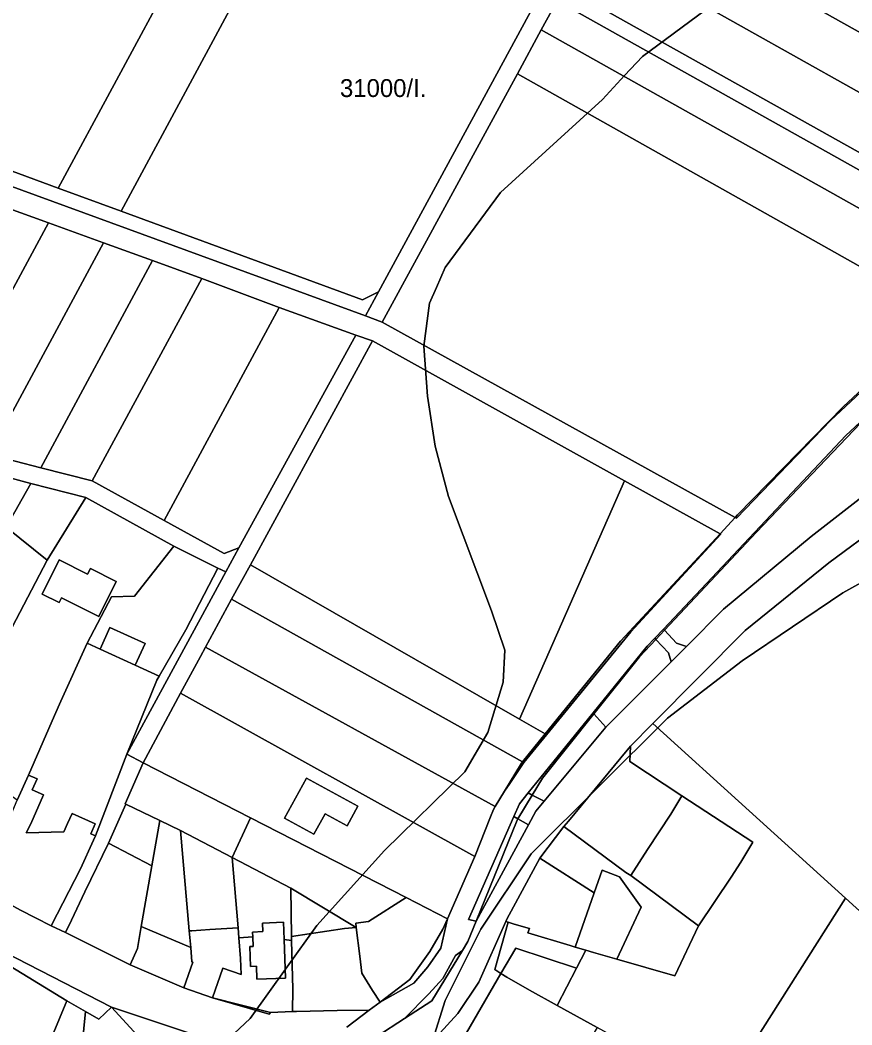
# Model space of a CAD drawing. Extents: x -541351 to -537540, y -1162694 to -1159725.
# Drawn here: x -538217.7 to -537985.1, y -1161335.8 to -1161054.8 of the extents above; entities that cross this region are included whole.
import ezdxf

# ---------------------------------------------------------------- set-up
doc = ezdxf.new("R2010")
doc.units = 0
for name, color, linetype in [('95560013', 7, 'Continuous'), ('95590013', 7, 'Continuous'), ('95610013', 7, 'Continuous'), ('95630013', 7, 'Continuous'), ('95640013', 7, 'Continuous'), ('95660013', 7, 'Continuous')]:
    doc.layers.add(name, color=color, linetype=linetype)

msp = doc.modelspace()

# ---------------------------------------------------------------- linework, layer by layer
at = {"layer": '95560013'}
for points in [[(-538246.11, -1161087.46), (-538182.74, -1160971.35), (-538141.8, -1160980.88), (-538207.03, -1161101.81), (-538233.61, -1161092.05)], [(-538141.8, -1160980.88), (-538123.2, -1160985.21), (-538189.43, -1161108.27), (-538207.03, -1161101.81)], [(-538050.98, -1161002.02), (-538049.53, -1161005.48), (-538117.46, -1161130.76), (-538121.93, -1161133.04), (-538189.43, -1161108.27), (-538123.2, -1160985.21)], [(-537903.69, -1161085.29), (-537915.45, -1161096.02), (-538051.5, -1161019.74), (-538044.43, -1161006.74)], [(-537941.41, -1161120.13), (-537948.57, -1161126.77), (-538071.97, -1161057.57), (-538067.56, -1161049.39)], [(-538071.97, -1161057.57), (-537948.57, -1161126.77), (-537959.49, -1161136.9), (-538078.6, -1161069.87)], [(-538017.76, -1161193.9), (-538116.49, -1161139.32), (-538078.6, -1161069.87), (-537959.49, -1161136.9), (-537987.47, -1161162.86), (-538017.1, -1161193.19)], [(-538166.87, -1161127.08), (-538145.25, -1161135.18), (-538177.41, -1161194.75), (-538197.52, -1161183.69)], [(-537862.95, -1161412.71), (-537904.74, -1161473.13), (-537909.29, -1161473.5), (-537958.26, -1161439.63), (-538014.16, -1161400.98), (-537997.12, -1161376.05), (-538023.45, -1161358.02), (-537986.93, -1161300.34), (-537910.48, -1161369.63)]]:
    msp.add_lwpolyline(points, close=True, dxfattribs=at)
msp.add_lwpolyline([(-537910.48, -1161369.63), (-537986.93, -1161300.34), (-538040.75, -1161251.55), (-538014.94, -1161225.48), (-537991.61, -1161206.61), (-537962.32, -1161184.95)], dxfattribs=at)
at = {"layer": '95590013'}
for points in [[(-537915.45, -1161096.02), (-537926.78, -1161106.53), (-538058.53, -1161032.66), (-538051.5, -1161019.74)], [(-537938.08, -1161117.04), (-538065.5, -1161045.58), (-538058.53, -1161032.66), (-537926.78, -1161106.53)], [(-537938.08, -1161117.04), (-537941.41, -1161120.13), (-538067.56, -1161049.39), (-538065.5, -1161045.58)], [(-538248.97, -1161170.34), (-538253.63, -1161166.17), (-538221.89, -1161107.13), (-538209.76, -1161111.53), (-538242.45, -1161172.06)], [(-538242.45, -1161172.06), (-538209.76, -1161111.53), (-538194.34, -1161117.12), (-538226.3, -1161176.33)], [(-538226.3, -1161176.33), (-538194.34, -1161117.12), (-538180.71, -1161122.06), (-538211.86, -1161180.02)], [(-538180.71, -1161122.06), (-538166.87, -1161127.08), (-538197.52, -1161183.69), (-538211.86, -1161180.02)], [(-538145.25, -1161135.18), (-538123.8, -1161142.88), (-538156.51, -1161202.37), (-538160.59, -1161204), (-538177.41, -1161194.75)], [(-538228.93, -1161180.63), (-538214.72, -1161184.39), (-538221.56, -1161196.64), (-538233.17, -1161188.12)], [(-538221.56, -1161196.64), (-538214.72, -1161184.39), (-538199.3, -1161188.32), (-538210.1, -1161205.84)], [(-538185.68, -1161215.95), (-538192.12, -1161216.12), (-538198.98, -1161229.08), (-538206.32, -1161245.29), (-538208.04, -1161249.25), (-538215.35, -1161265.95), (-538218.47, -1161272.98), (-538226.43, -1161267.38), (-538222.55, -1161258.47), (-538228.24, -1161255.93), (-538232.5, -1161265.65), (-538239.68, -1161262.59), (-538233.03, -1161249.61), (-538210.1, -1161205.84), (-538199.3, -1161188.32), (-538174.67, -1161201.96)], [(-538221.56, -1161196.64), (-538210.1, -1161205.84), (-538233.03, -1161249.61), (-538242.07, -1161245.33), (-538252.02, -1161240.61), (-538234.58, -1161212.88), (-538229.57, -1161215.15), (-538226.63, -1161208.69), (-538231.63, -1161206.42)], [(-538182.74, -1161229.12), (-538192.57, -1161224.66), (-538195.33, -1161230.76), (-538198.98, -1161229.08), (-538192.12, -1161216.12), (-538185.68, -1161215.95), (-538174.67, -1161201.96), (-538162.39, -1161208.04), (-538171.35, -1161225.31), (-538178.84, -1161238.26), (-538185.51, -1161235.2)], [(-538206.11, -1161216.38), (-538195.64, -1161221.58), (-538190.79, -1161211.81), (-538198.04, -1161208.21), (-538198.8, -1161209.74), (-538206.77, -1161205.78), (-538211.53, -1161215.36), (-538206.78, -1161217.72)], [(-538171.35, -1161225.31), (-538162.39, -1161208.04), (-538160.18, -1161209.13), (-538187.83, -1161260.14), (-538179.48, -1161239.38), (-538178.84, -1161238.26)], [(-538082.21, -1161270.41), (-538084.82, -1161274.71), (-538165.84, -1161230.16), (-538158.58, -1161216.8), (-538077.18, -1161262.24), (-538077.49, -1161262.62)], [(-538172.84, -1161243.04), (-538167.26, -1161232.77), (-538165.84, -1161230.16), (-538084.82, -1161274.71), (-538085.32, -1161275.54), (-538086.13, -1161277.58), (-538090.55, -1161288.74)], [(-538153.25, -1161277.88), (-538183.26, -1161262.48), (-538172.84, -1161243.04), (-538090.55, -1161288.74), (-538098.16, -1161306.15), (-538109.73, -1161300.22)], [(-538048.87, -1161340.61), (-538056.37, -1161336.5), (-538067.49, -1161330.41), (-538062.1, -1161319.97), (-538059.49, -1161314.92), (-538057.35, -1161315.54), (-538050.81, -1161317.42), (-538034.67, -1161322.06), (-538028, -1161308.15), (-538018.91, -1161294.47), (-538016.19, -1161290.33), (-538012.78, -1161284.73), (-538032.67, -1161271.71), (-538047.23, -1161262.17), (-538047.04, -1161257.9), (-538040.75, -1161251.55), (-537986.93, -1161300.34), (-538023.45, -1161358.02)], [(-538032.67, -1161271.71), (-538035.76, -1161276.86), (-538042.23, -1161286.72), (-538046.89, -1161294), (-538048.32, -1161293.16), (-538065.66, -1161280.36), (-538064.4, -1161278.84), (-538049.68, -1161261.08), (-538047.04, -1161257.9), (-538047.23, -1161262.17)], [(-538183.26, -1161262.48), (-538153.25, -1161277.88), (-538158.35, -1161289.03), (-538172.86, -1161281.42), (-538178.64, -1161278.63), (-538188.09, -1161274.06), (-538188.28, -1161273.97)], [(-538123.25, -1161274.64), (-538137.61, -1161266.79), (-538143.78, -1161277.98), (-538135.54, -1161282.51), (-538132.37, -1161276.76), (-538126.24, -1161280.1)], [(-538169.99, -1161314.15), (-538183.84, -1161308.34), (-538180.86, -1161291.3), (-538178.64, -1161278.63), (-538172.86, -1161281.42), (-538170.44, -1161309.54)], [(-538123.73, -1161308.57), (-538141.98, -1161297.6), (-538158.35, -1161289.03), (-538153.25, -1161277.88), (-538109.73, -1161300.22), (-538120.27, -1161306.94), (-538123.84, -1161307.38)], [(-538050.07, -1161294.4), (-538054.93, -1161292.56), (-538057.14, -1161298.88), (-538072.34, -1161289.23), (-538065.66, -1161280.36), (-538048.32, -1161293.16), (-538046.89, -1161294), (-538028, -1161308.15), (-538034.67, -1161322.06), (-538050.81, -1161317.42), (-538044.08, -1161302.9)], [(-538172.86, -1161281.42), (-538158.35, -1161289.03), (-538156.75, -1161308.71), (-538164.64, -1161309.17), (-538169.67, -1161309.49), (-538170.44, -1161309.54)], [(-538141.98, -1161297.6), (-538141.83, -1161311.11), (-538141.82, -1161312.2), (-538143.89, -1161311.92), (-538144.07, -1161307.13), (-538149.89, -1161307.33), (-538149.78, -1161309.71), (-538152.71, -1161309.85), (-538152.66, -1161311.14), (-538156.52, -1161311.46), (-538156.75, -1161308.71), (-538158.35, -1161289.03)], [(-538141.83, -1161311.11), (-538141.98, -1161297.6), (-538123.73, -1161308.57), (-538127.02, -1161308.88)], [(-538067.49, -1161330.41), (-538075.29, -1161326.14), (-538081.56, -1161322.5), (-538083.28, -1161321.48), (-538079.07, -1161314.31), (-538062.1, -1161319.97)], [(-538201.63, -1161354.88), (-538202.9, -1161363.74), (-538204.4, -1161363.88), (-538203.87, -1161369.63), (-538205.58, -1161379.99), (-538216.91, -1161379.32), (-538216.87, -1161370.22), (-538212.13, -1161351.43), (-538208.75, -1161339), (-538204.65, -1161329.08), (-538199.37, -1161332.11)]]:
    msp.add_lwpolyline(points, close=True, dxfattribs=at)
at = {"layer": '95610013'}
for points in [[(-537996.47, -1161199.19), (-538020.98, -1161219.57), (-538031.39, -1161229.99), (-538034.17, -1161229.06), (-538037.53, -1161225.44), (-538011.8, -1161198.06), (-537982.73, -1161167.56), (-537948.84, -1161136.22), (-537936.28, -1161153.8), (-537968.86, -1161177.68)], [(-538153.28, -1161207.14), (-538119.15, -1161144.52), (-538048.69, -1161183.64), (-538078.07, -1161250.34)], [(-538070.89, -1161254.46), (-538078.07, -1161250.34), (-538048.69, -1161183.64), (-538021.99, -1161198.46), (-538049.86, -1161228.47)], [(-538070.89, -1161254.46), (-538077.18, -1161262.24), (-538158.58, -1161216.8), (-538153.28, -1161207.14), (-538078.07, -1161250.34)], [(-538036.42, -1161231.78), (-538039.94, -1161228.01), (-538037.53, -1161225.44), (-538034.17, -1161229.06), (-538031.39, -1161229.99), (-538035.64, -1161234.24)], [(-538039.94, -1161228.01), (-538036.42, -1161231.78), (-538035.64, -1161234.24), (-538053.92, -1161252.54), (-538057.25, -1161248.83), (-538044.49, -1161232.86)]]:
    msp.add_lwpolyline(points, close=True, dxfattribs=at)
at = {"layer": '95630013'}
for points in [[(-537867.27, -1161068.59), (-537867, -1161069.02), (-537887.98, -1161079.94), (-537948.84, -1161136.22), (-537982.73, -1161167.56), (-538011.8, -1161198.06), (-538037.53, -1161225.44), (-538037.84, -1161225.1), (-537986.78, -1161171.01), (-537949.05, -1161135.92), (-537888.93, -1161079.99)], [(-538017.1, -1161193.19), (-537987.47, -1161162.86), (-537959.49, -1161136.9), (-537959.19, -1161137.07), (-537990.97, -1161166.65), (-538017.4, -1161194.1), (-538017.76, -1161193.9)], [(-538076.87, -1161262.41), (-538077.18, -1161262.24), (-538070.89, -1161254.46), (-538049.86, -1161228.47), (-538021.99, -1161198.46), (-538021.73, -1161198.6), (-538046.97, -1161225.92)], [(-538039.94, -1161228.01), (-538040.26, -1161227.67), (-538037.84, -1161225.1), (-538037.53, -1161225.44)], [(-538044.49, -1161232.86), (-538057.25, -1161248.83), (-538057.48, -1161248.57), (-538042.4, -1161229.94), (-538040.26, -1161227.67), (-538039.94, -1161228.01)], [(-538071.63, -1161266.84), (-538074.49, -1161271.55), (-538075.61, -1161270.96), (-538057.48, -1161248.57), (-538057.25, -1161248.83)], [(-538082.21, -1161270.41), (-538077.49, -1161262.62), (-538077.18, -1161262.24), (-538076.87, -1161262.41), (-538080.78, -1161268.27)], [(-538074.49, -1161271.55), (-538078.51, -1161278.18), (-538079.64, -1161277.56), (-538078.09, -1161274.02), (-538075.61, -1161270.96)], [(-538092.28, -1161306.35), (-538079.64, -1161277.56), (-538078.51, -1161278.18), (-538078.74, -1161278.56), (-538090.17, -1161306.77)], [(-538098.16, -1161306.15), (-538100.05, -1161314.32), (-538103.67, -1161319.58), (-538107.62, -1161324.11), (-538117.04, -1161329.42), (-538108.69, -1161323.1), (-538103.16, -1161315.27), (-538099.45, -1161309.07)], [(-538094.04, -1161315.05), (-538102.54, -1161329.13), (-538110.22, -1161334.06), (-538103.41, -1161327.15), (-538099.5, -1161322.86), (-538095.94, -1161316.37)]]:
    msp.add_lwpolyline(points, close=True, dxfattribs=at)
for points in [[(-538292.2, -1161074.93), (-538121.13, -1161137.53), (-538116.49, -1161139.32), (-538017.76, -1161193.9), (-538021.99, -1161198.46), (-538048.69, -1161183.64), (-538119.15, -1161144.52), (-538123.8, -1161142.88), (-538145.25, -1161135.18), (-538166.87, -1161127.08), (-538180.71, -1161122.06), (-538194.34, -1161117.12), (-538209.76, -1161111.53), (-538221.89, -1161107.13)], [(-538126.38, -1161336.49), (-538120.06, -1161331.71), (-538117.04, -1161329.42), (-538107.62, -1161324.11), (-538103.67, -1161319.58), (-538100.05, -1161314.32), (-538098.16, -1161306.15), (-538090.55, -1161288.74), (-538086.13, -1161277.58), (-538085.32, -1161275.54), (-538084.82, -1161274.71), (-538082.21, -1161270.41), (-538080.78, -1161268.27), (-538076.87, -1161262.41), (-538046.97, -1161225.92), (-538021.73, -1161198.6), (-538021.99, -1161198.46), (-538017.76, -1161193.9), (-538017.4, -1161194.1), (-537990.97, -1161166.65), (-537959.19, -1161137.07)], [(-537949.05, -1161135.92), (-537986.78, -1161171.01), (-538037.84, -1161225.1), (-538040.26, -1161227.67), (-538042.4, -1161229.94), (-538057.48, -1161248.57), (-538075.61, -1161270.96), (-538078.09, -1161274.02), (-538079.64, -1161277.56), (-538092.28, -1161306.35), (-538090.17, -1161306.77), (-538092.49, -1161312.48), (-538094.04, -1161315.05), (-538095.94, -1161316.37), (-538099.5, -1161322.86), (-538103.41, -1161327.15), (-538110.22, -1161334.06), (-538117.98, -1161339.05)]]:
    msp.add_lwpolyline(points, dxfattribs=at)
at = {"layer": '95640013'}
for points in [[(-538049.53, -1161005.48), (-538050.98, -1161002.02), (-538039.9, -1161004.61), (-538044.43, -1161006.74), (-538051.5, -1161019.74), (-538058.53, -1161032.66), (-538065.5, -1161045.58), (-538067.56, -1161049.39), (-538071.97, -1161057.57), (-538078.6, -1161069.87), (-538116.49, -1161139.32), (-538121.13, -1161137.53), (-538117.46, -1161130.76)], [(-538119.15, -1161144.52), (-538153.28, -1161207.14), (-538158.58, -1161216.8), (-538165.84, -1161230.16), (-538167.26, -1161232.77), (-538172.84, -1161243.04), (-538183.26, -1161262.48), (-538187.83, -1161260.14), (-538160.18, -1161209.13), (-538156.51, -1161202.37), (-538123.8, -1161142.88)], [(-538206.78, -1161217.72), (-538211.53, -1161215.36), (-538206.77, -1161205.78), (-538198.8, -1161209.74), (-538198.04, -1161208.21), (-538190.79, -1161211.81), (-538195.64, -1161221.58), (-538206.11, -1161216.38)], [(-538192.57, -1161224.66), (-538182.74, -1161229.12), (-538185.51, -1161235.2), (-538195.33, -1161230.76)], [(-538208.04, -1161249.25), (-538206.32, -1161245.29), (-538198.98, -1161229.08), (-538195.33, -1161230.76), (-538185.51, -1161235.2), (-538178.84, -1161238.26), (-538179.48, -1161239.38), (-538187.83, -1161260.14), (-538196.6, -1161282.98), (-538197.91, -1161282.41), (-538196.73, -1161279.61), (-538203.14, -1161276.7), (-538204.45, -1161279.52), (-538205.49, -1161281.78), (-538216.01, -1161282.13), (-538214.7, -1161279.55), (-538211.13, -1161271.46), (-538214.28, -1161270.05), (-538212.96, -1161267), (-538215.35, -1161265.95)], [(-538074.49, -1161271.55), (-538071.63, -1161266.84), (-538057.25, -1161248.83), (-538053.92, -1161252.54), (-538071.16, -1161273.29)], [(-538200.82, -1161292.15), (-538197.13, -1161284.14), (-538196.6, -1161282.98), (-538187.83, -1161260.14), (-538183.26, -1161262.48), (-538188.28, -1161273.97), (-538188.09, -1161274.06), (-538192.99, -1161284.98), (-538199.55, -1161298.56), (-538203.3, -1161306.56), (-538204.96, -1161309.98), (-538209.04, -1161308.12)], [(-538196.6, -1161282.98), (-538197.13, -1161284.14), (-538200.82, -1161292.15), (-538209.04, -1161308.12), (-538213.35, -1161305.89), (-538217.56, -1161303.7), (-538231.47, -1161296.16), (-538228.59, -1161291.79), (-538227.33, -1161289.9), (-538224.32, -1161285.3), (-538220.21, -1161276.97), (-538218.47, -1161272.98), (-538215.35, -1161265.95), (-538212.96, -1161267), (-538214.28, -1161270.05), (-538211.13, -1161271.46), (-538214.7, -1161279.55), (-538216.01, -1161282.13), (-538205.49, -1161281.78), (-538204.45, -1161279.52), (-538203.14, -1161276.7), (-538196.73, -1161279.61), (-538197.91, -1161282.41)], [(-538143.78, -1161277.98), (-538137.61, -1161266.79), (-538123.25, -1161274.64), (-538126.24, -1161280.1), (-538132.37, -1161276.76), (-538135.54, -1161282.51)], [(-538075.51, -1161279.83), (-538078.51, -1161278.18), (-538074.49, -1161271.55), (-538071.16, -1161273.29), (-538073.45, -1161276.05)], [(-538012.78, -1161284.73), (-538016.19, -1161290.33), (-538018.91, -1161294.47), (-538028, -1161308.15), (-538046.89, -1161294), (-538042.23, -1161286.72), (-538035.76, -1161276.86), (-538032.67, -1161271.71)], [(-538192.99, -1161284.98), (-538188.09, -1161274.06), (-538178.64, -1161278.63), (-538180.86, -1161291.3)], [(-538192.16, -1161330.85), (-538195.72, -1161334.2), (-538199.37, -1161332.11), (-538204.65, -1161329.08), (-538229.72, -1161313.75), (-538236.28, -1161309.78), (-538238.78, -1161308.21), (-538245.54, -1161304.08), (-538251.65, -1161301.22), (-538274.94, -1161293.48), (-538276.06, -1161296.55), (-538307.06, -1161285.3), (-538308.93, -1161290.39), (-538312.04, -1161297.25), (-538308.26, -1161282.74), (-538303.02, -1161280.34), (-538245.31, -1161303.55)], [(-538078.74, -1161278.56), (-538078.51, -1161278.18), (-538075.51, -1161279.83), (-538090.17, -1161306.77)], [(-538204.96, -1161309.98), (-538203.3, -1161306.56), (-538199.55, -1161298.56), (-538192.99, -1161284.98), (-538180.86, -1161291.3), (-538183.84, -1161308.34), (-538184.9, -1161314.44), (-538186.92, -1161319.02)], [(-538081.21, -1161307.11), (-538081.87, -1161306.89), (-538081.57, -1161306.27), (-538072.34, -1161289.23), (-538057.14, -1161298.88), (-538062.46, -1161314.06), (-538063.88, -1161313.65), (-538075.74, -1161310.03), (-538075.3, -1161308.85), (-538079.54, -1161307.64)], [(-538062.46, -1161314.06), (-538057.14, -1161298.88), (-538054.93, -1161292.56), (-538050.07, -1161294.4), (-538044.08, -1161302.9), (-538050.81, -1161317.42), (-538057.35, -1161315.54), (-538059.49, -1161314.92)], [(-538099.45, -1161309.07), (-538103.16, -1161315.27), (-538108.69, -1161323.1), (-538117.04, -1161329.42), (-538119.12, -1161326.23), (-538122.13, -1161321.3), (-538122.7, -1161316.63), (-538123.73, -1161308.57), (-538123.84, -1161307.38), (-538120.27, -1161306.94), (-538109.73, -1161300.22), (-538098.16, -1161306.15)], [(-538184.9, -1161314.44), (-538183.84, -1161308.34), (-538169.99, -1161314.15), (-538169.7, -1161318.14), (-538169.42, -1161318.24), (-538171.94, -1161325.41), (-538186.92, -1161319.02)], [(-538164.64, -1161309.17), (-538156.75, -1161308.71), (-538156.52, -1161311.46), (-538156.05, -1161317.28), (-538155.88, -1161321.68), (-538161.01, -1161319.93), (-538163.93, -1161328.23), (-538171.94, -1161325.41), (-538169.42, -1161318.24), (-538169.7, -1161318.14), (-538169.99, -1161314.15), (-538170.44, -1161309.54), (-538169.67, -1161309.49)], [(-538149.89, -1161307.33), (-538144.07, -1161307.13), (-538143.89, -1161311.92), (-538143.48, -1161322.72), (-538151.47, -1161322.99), (-538151.61, -1161319.39), (-538153.23, -1161319.47), (-538153.43, -1161313.86), (-538152.54, -1161313.85), (-538152.66, -1161311.14), (-538152.71, -1161309.85), (-538149.78, -1161309.71)], [(-538119.12, -1161326.23), (-538117.04, -1161329.42), (-538120.06, -1161331.71), (-538129.01, -1161331.79), (-538140.41, -1161332.05), (-538141.49, -1161332.07), (-538141.4, -1161325.86), (-538141.82, -1161312.2), (-538141.83, -1161311.11), (-538127.02, -1161308.88), (-538123.73, -1161308.57), (-538122.7, -1161316.63), (-538122.13, -1161321.3)], [(-538079.07, -1161314.31), (-538083.28, -1161321.48), (-538084.91, -1161320.36), (-538081.21, -1161307.11), (-538079.54, -1161307.64), (-538075.3, -1161308.85), (-538075.74, -1161310.03), (-538063.88, -1161313.65), (-538062.46, -1161314.06), (-538059.49, -1161314.92), (-538062.1, -1161319.97)], [(-538141.49, -1161332.07), (-538147.7, -1161332.31), (-538163.93, -1161328.23), (-538161.01, -1161319.93), (-538155.88, -1161321.68), (-538156.05, -1161317.28), (-538156.52, -1161311.46), (-538152.66, -1161311.14), (-538152.54, -1161313.85), (-538153.43, -1161313.86), (-538153.23, -1161319.47), (-538151.61, -1161319.39), (-538151.47, -1161322.99), (-538143.48, -1161322.72), (-538143.89, -1161311.92), (-538141.82, -1161312.2), (-538141.4, -1161325.86)], [(-538238, -1161339.58), (-538243.31, -1161337.08), (-538234.2, -1161321.15), (-538229.72, -1161313.75), (-538204.65, -1161329.08), (-538208.75, -1161339), (-538212.13, -1161351.43), (-538224.22, -1161347.08), (-538226.69, -1161345.13), (-538229.72, -1161351.24), (-538236.23, -1161348.01), (-538233.2, -1161341.9)], [(-538056.37, -1161336.5), (-538072.11, -1161362.66), (-538074.35, -1161361.36), (-538089.39, -1161352.67), (-538098.33, -1161347.51), (-538083.28, -1161321.48), (-538081.56, -1161322.5), (-538075.29, -1161326.14), (-538067.49, -1161330.41)], [(-538163.93, -1161328.23), (-538147.7, -1161332.31), (-538148.03, -1161332.81)], [(-538193.79, -1161353.93), (-538201.63, -1161354.88), (-538199.37, -1161332.11), (-538195.72, -1161334.2), (-538192.16, -1161330.85), (-538182.83, -1161341.02), (-538181.48, -1161342.49), (-538184.8, -1161345.68)]]:
    msp.add_lwpolyline(points, close=True, dxfattribs=at)
for points in [[(-538233.61, -1161092.05), (-538207.03, -1161101.81), (-538189.43, -1161108.27), (-538121.93, -1161133.04), (-538117.46, -1161130.76), (-538121.13, -1161137.53), (-538292.2, -1161074.93)], [(-538170.56, -1161338.04), (-538192.16, -1161330.85), (-538245.31, -1161303.55), (-538303.02, -1161280.34), (-538330.75, -1161269.19), (-538324.12, -1161285.82), (-538325.1, -1161302.89), (-538326.63, -1161287.66), (-538329.39, -1161277.17), (-538345.34, -1161270.42), (-538357.37, -1161259.2), (-538373.1, -1161240.95), (-538390.5, -1161221.38), (-538407.04, -1161203.36), (-538407.38, -1161203.61), (-538422.64, -1161185.64), (-538435.52, -1161164.53), (-538447.63, -1161142.88), (-538457.08, -1161125.62), (-538459.07, -1161122.1), (-538466.64, -1161107.89), (-538471, -1161099.7), (-538478.18, -1161085.45), (-538480.58, -1161080.62)], [(-538226.3, -1161176.33), (-538211.86, -1161180.02), (-538197.52, -1161183.69), (-538177.41, -1161194.75), (-538160.59, -1161204), (-538156.51, -1161202.37), (-538160.18, -1161209.13), (-538162.39, -1161208.04), (-538174.67, -1161201.96), (-538199.3, -1161188.32), (-538214.72, -1161184.39), (-538228.93, -1161180.63)], [(-538117.98, -1161339.05), (-538110.22, -1161334.06), (-538102.54, -1161329.13), (-538094.04, -1161315.05), (-538092.49, -1161312.48), (-538090.17, -1161306.77), (-538075.51, -1161279.83), (-538073.45, -1161276.05), (-538071.16, -1161273.29), (-538053.92, -1161252.54), (-538035.64, -1161234.24), (-538031.39, -1161229.99), (-538020.98, -1161219.57), (-537996.47, -1161199.19), (-537968.86, -1161177.68)], [(-537962.32, -1161184.95), (-537991.61, -1161206.61), (-538014.94, -1161225.48), (-538040.75, -1161251.55), (-538047.04, -1161257.9), (-538049.68, -1161261.08), (-538064.4, -1161278.84), (-538065.66, -1161280.36), (-538072.34, -1161289.23), (-538081.57, -1161306.27), (-538081.87, -1161306.89), (-538089.44, -1161323.89), (-538095.33, -1161332.64), (-538103.2, -1161341.32)], [(-538231.47, -1161296.16), (-538217.56, -1161303.7), (-538213.35, -1161305.89), (-538209.04, -1161308.12), (-538204.96, -1161309.98), (-538186.92, -1161319.02), (-538171.94, -1161325.41), (-538163.93, -1161328.23), (-538148.03, -1161332.81), (-538147.7, -1161332.31), (-538141.49, -1161332.07), (-538140.41, -1161332.05), (-538129.01, -1161331.79), (-538120.06, -1161331.71), (-538126.38, -1161336.49)], [(-538103.2, -1161341.32), (-538095.33, -1161332.64), (-538089.44, -1161323.89), (-538081.87, -1161306.89), (-538081.21, -1161307.11), (-538084.91, -1161320.36), (-538083.28, -1161321.48), (-538098.33, -1161347.51)], [(-538182.83, -1161341.02), (-538192.16, -1161330.85), (-538170.56, -1161338.04)]]:
    msp.add_lwpolyline(points, dxfattribs=at)
at = {"layer": '95660013'}
for points in [[(-538026.12, -1161052), (-538043.69, -1161065), (-538048.66, -1161070.33), (-538054.87, -1161077), (-538083.37, -1161103), (-538098.87, -1161124), (-538101.27, -1161129.56), (-538103.19, -1161134), (-538104.81, -1161146), (-538103.81, -1161160), (-538101.62, -1161174), (-538097.87, -1161188), (-538085.87, -1161220), (-538082.12, -1161231), (-538082.62, -1161240), (-538086.87, -1161254), (-538093.31, -1161265), (-538115.81, -1161287), (-538134.69, -1161308), (-538142.99, -1161319.56), (-538153.37, -1161334), (-538184.31, -1161363)], [(-538184.31, -1161363), (-538153.37, -1161334), (-538142.99, -1161319.56), (-538134.69, -1161308), (-538115.81, -1161287), (-538093.31, -1161265), (-538086.87, -1161254), (-538082.62, -1161240), (-538082.12, -1161231), (-538085.87, -1161220), (-538097.87, -1161188), (-538101.62, -1161174), (-538103.81, -1161160), (-538104.81, -1161146), (-538103.19, -1161134), (-538101.27, -1161129.56), (-538098.87, -1161124), (-538083.37, -1161103), (-538054.87, -1161077), (-538048.66, -1161070.33), (-538043.69, -1161065), (-538026.12, -1161052)], [(-538102.31, -1161340), (-538098.81, -1161329), (-538088.87, -1161309), (-538074.81, -1161288), (-538036.69, -1161250), (-538015.81, -1161234), (-537987.62, -1161215), (-537964.37, -1161202)], [(-537964.37, -1161202), (-537987.62, -1161215), (-538015.81, -1161234), (-538036.69, -1161250), (-538074.81, -1161288), (-538088.87, -1161309), (-538098.81, -1161329), (-538102.31, -1161340)]]:
    msp.add_lwpolyline(points, dxfattribs=at)

# ---------------------------------------------------------------- texts
msp.add_text('31000/I.', height=5, rotation=0, dxfattribs=at).set_placement((-538128.25, -1161076.32))

doc.saveas('drawing.dxf')
